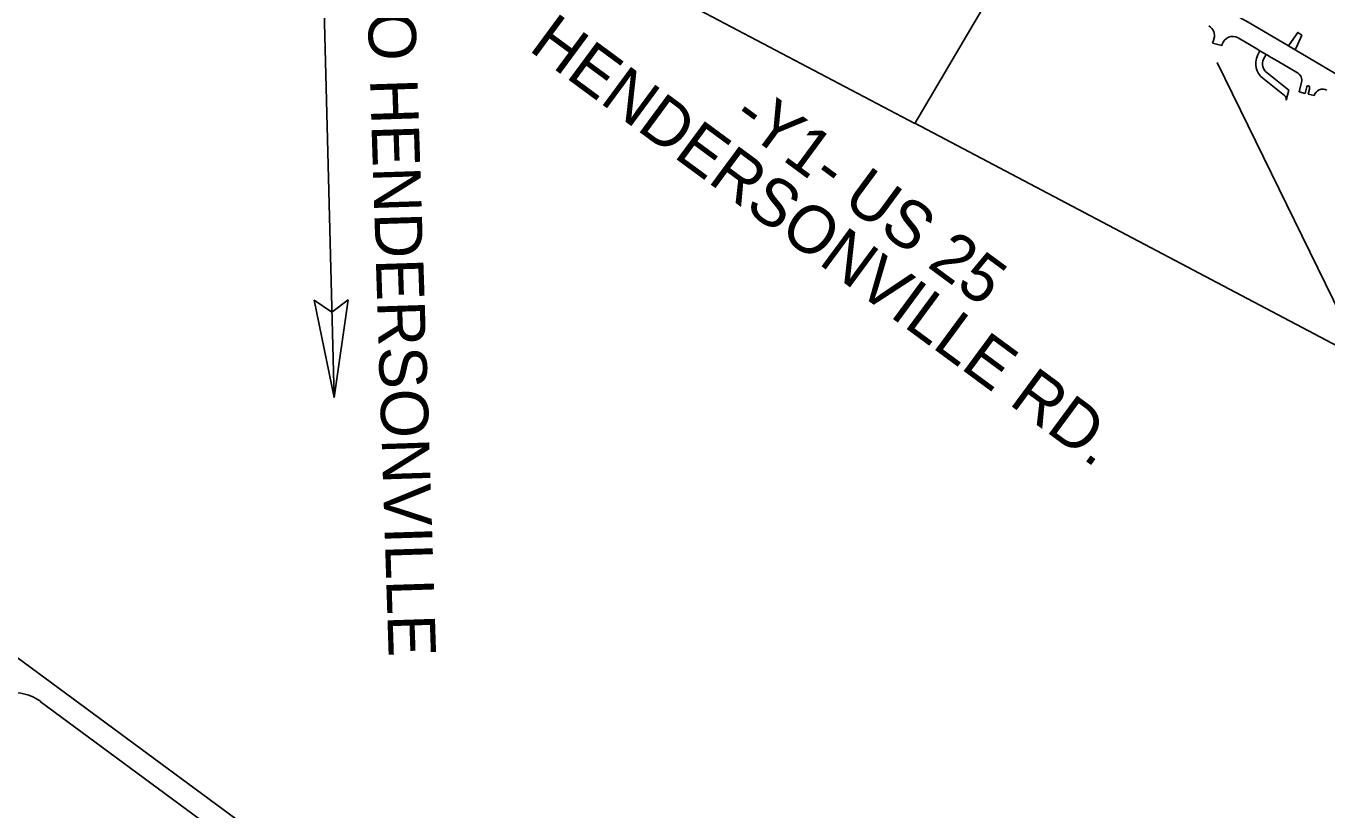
# Model space of a CAD drawing. Extents: x 945666 to 965748, y 644452 to 663300.
# Drawn here: x 951483 to 954496, y 652491 to 654307 of the extents above; entities that cross this region are included whole.
import ezdxf

# ---------------------------------------------------------------- set-up
doc = ezdxf.new("R2010")
doc.units = 0
for name, color, linetype in [('Old_Level_23', 7, 'Continuous'), ('Prop EOT', 7, 'Continuous'), ('Prop Shade Light', 7, 'Continuous'), ('Prop Terminator CELL', 7, 'Continuous'), ('Sheet Plan Layout CELL', 7, 'Continuous'), ('Sheet Title CELL', 7, 'Continuous')]:
    doc.layers.add(name, color=color, linetype=linetype)

msp = doc.modelspace()

# ---------------------------------------------------------------- linework, layer by layer
at = {"layer": 'Old_Level_23'}
for p, q in [((952170.9, 654438.9), (952196.4, 653446.7)), ((954241.6, 654222.8), (954832.4, 653013.2))]:
    msp.add_line(p, q, dxfattribs=at)
at = {"layer": 'Prop EOT'}
for p, q in [((954413.2, 654271.5), (954406.4, 654261.1)), ((954427, 654263.4), (954421.9, 654251.9)), ((954335, 654238.7), (954340.1, 654250.2)), ((954348.8, 654230.6), (954354.6, 654241.6))]:
    msp.add_line(p, q, dxfattribs=at)
at = {"layer": 'Prop Shade Light'}
for p, q in [((954231.5, 654269.8), (954230.9, 654267.6)), ((954230.9, 654267.6), (954252.2, 654261.9)), ((954252.2, 654261.9), (954252.7, 654264)), ((954289.8, 654279.8), (954333.3, 654254.2)), ((954413.2, 654271.6), (954406.4, 654261.1)), ((954406.4, 654261.1), (954421.9, 654252)), ((954421.9, 654252), (954427, 654263.4)), ((954340.1, 654250.2), (954334.9, 654238.7)), ((954354.6, 654241.7), (954340.1, 654250.2)), ((954348.8, 654230.6), (954354.6, 654241.7)), ((954359.3, 654238.9), (954362.4, 654237)), ((954362.4, 654237), (954365.2, 654235.4)), ((954365.2, 654235.4), (954374.6, 654229.9)), ((954374.6, 654229.9), (954406.9, 654210.9)), ((954406.9, 654210.9), (954427.3, 654198.9)), ((954346.9, 654186.2), (954397.5, 654146.1)), ((954407, 654159), (954356.8, 654198.7)), ((954436.5, 654176.9), (954431.1, 654154.8)), ((954401, 654135.9), (954407, 654159)), ((954431.1, 654154.8), (954445.4, 654151.2)), ((954445.4, 654151.2), (954449.1, 654166.4)), ((954454.8, 654161.3), (954452, 654149.7)), ((954452, 654149.7), (954466.1, 654146.2)), ((954455.5, 654164.8), (954454.8, 654161.3))]:
    msp.add_line(p, q, dxfattribs=at)
for points in [[(954623.6, 654133.3), (954421.9, 654252), (954406.4, 654261.1), (954313.3, 654315.9), (954298, 654324.8), (954227.6, 654366.3)], [(954427, 654263.4), (954437.2, 654286.1), (954427.8, 654292.6), (954413.2, 654271.6)], [(954333.3, 654254.2), (954340.1, 654250.2), (954354.6, 654241.7), (954359.3, 654238.9)]]:
    msp.add_lwpolyline(points, dxfattribs=at)
for centre, radius, start, end in [((954210.1, 654285.6), 25, 341.9899, 60.7704), ((954391.8, 654226.5), 166, 161.9899, 164.8917), ((954391.8, 654226.5), 144, 164.5161, 164.8917), ((954277.1, 654258.3), 25, 59.525, 164.5161), ((954373.6, 654219.9), 43, 153.995, 231.6556), ((954373.6, 654219.9), 27, 156.6551, 231.6556), ((954417.1, 654181.7), 20, 346.1716, 59.525), ((954391.3, 654138.3), 10, 346.1792, 51.6556), ((954452.3, 654165.6), 3.3, 347.135, 166.0318), ((954485.5, 654141.4), 20, 59.525, 166.1716)]:
    msp.add_arc(centre, radius, start, end, dxfattribs=at)
at = {"layer": 'Prop Terminator CELL'}
msp.add_lwpolyline([(952229.4, 653672.6), (952196.4, 653446.7), (952150.6, 653671.8), (952191.3, 653644.1)], close=True, dxfattribs=at)
at = {"layer": 'Sheet Plan Layout CELL'}
for p, q in [((954074.6, 654988.1), (953541, 654081.3)), ((952452.4, 654656.1), (953541, 654081.3)), ((953541.5, 654082.2), (954706.6, 653467.1))]:
    msp.add_line(p, q, dxfattribs=at)
at = {"layer": 'Sheet Title CELL'}
for p, q in [((948809.3, 654800.8), (960237.5, 646372.5)), ((951515.9, 652742.4), (954574.1, 650487))]:
    msp.add_line(p, q, dxfattribs=at)
msp.add_arc((951456.9, 652662.4), 100, 53.5908, 143.5908, dxfattribs=at)

# ---------------------------------------------------------------- texts
at = {"layer": 'Old_Level_23'}
for s, rotation, p in [('TO HENDERSONVILLE', 271.8558, (952271.6, 654429.2)), ('HENDERSONVILLE RD.', 323.5908, (952644.5, 654252.6)), ('-Y1- US 25', 323.5908, (953113.4, 654086))]:
    msp.add_text(s, height=110, rotation=rotation, dxfattribs=at).set_placement(p)

doc.saveas('drawing.dxf')
